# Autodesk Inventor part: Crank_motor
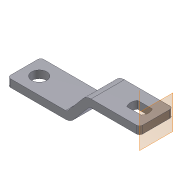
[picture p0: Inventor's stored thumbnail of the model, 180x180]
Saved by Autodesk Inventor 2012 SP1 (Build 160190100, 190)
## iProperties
Created: 2006-03
Part Number: Crank_motor
Document SubType Name: Modeling
Material: Stainless Steel, 440C
Mass: 73.5464 g
Surface Area: 52.6545 cm^2
Volume: 9.48986 cm^3
Density: 7.75 g/cm^3
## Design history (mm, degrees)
sketch "Sketch1"
  geometry: L1 (0, 0)-(-34.15, 0); L2 (0, 0)-(12.586, -15); L3 (12.586, -15)-(53.05, -15)
  constraints: 6 end point, 1 horizontal, 1 parallel
  dimensions: "d0" = 130 deg angle of L2 L1; "d1" = 87.2 horizontal distance of L3.end L1.end; "d2" = 34.15 distance of L1.start L1.end; "d3" = 15 distance between parallel lines of L3 L1
workplane "Work Plane1"
sketch "Sketch2"
  geometry: L1 (-11, 2.5)-(11, 2.5); L2 (11, 2.5)-(11, -2.5); L3 (11, -2.5)-(-11, -2.5); L4 (-11, -2.5)-(-11, 2.5); L5 (-11, 2.5)-(11, -2.5); 2 further points
  constraints: 10 end point, 2 parallel, 1 coincident, 1 horizontal, 1 midpoint, 1 perpendicular
  dimensions: "d4" = 22 distance of L1.start L1.end; "d5" = 5 distance of L3.end L1.start
sweep "Sweep1" sketch "Sketch2" dims "d6" = 0
fillet "Fillet1" dims "d7" = 7
fillet "Fillet2" dims "d8" = 2
sketch "Sketch4"
  geometry: L1 (-95.92, 11)-(26.16, 11) reference; L2 (0, 28.6)-(0, -2.2) reference; L3 (-15.823, 7.425)-(-6.178, 7.425); L4 (-6.178, 7.425)-(-6.178, 14.575); L5 (-6.178, 14.575)-(-15.823, 14.575); L6 (-15.823, 14.575)-(-15.823, 7.425); L7 (-15.823, 7.425)-(-6.178, 14.575); A1 r 6 centre (-10.997, 11) between (-6.178, 7.425) and (-6.178, 14.575); A2 r 6 centre (-11.004, 11) between (-15.823, 14.575) and (-15.823, 7.425); 2 further points
  constraints: 10 end point, 4 point on circle, 3 point on line, 2 centre point, 2 parallel, 1 equal radius, 1 horizontal, 1 midpoint, 1 perpendicular
  dimensions: "d18" = 9.645 distance of L3.start L3.end; "d19" = 7.15 distance of L5.end L3.start; "d20" = 6.178 distance from line of L3.end L2; "d21" = 6 radius of A2
extrude "Extrusion3" cut sketch "Sketch4" stored distance "d22" = 10; taper "d23" = 0 deg
sketch "Sketch3"
  geometry: L1 (-8.72, 11)-(113.36, 11) reference; L2 (0, 22)-(0, 0) reference; C1 r 5 at (10, 11); 1 further point
  constraints: 1 centre point, 1 point on line
  dimensions: "d9" = 10 distance from line of C1.centre L2; "d10" = 10 diameter of C1
extrude "Extrusion1" cut sketch "Sketch3" stored distance "d11" = 10; taper "d12" = 0 deg
fillet "Fillet3" dims "d17" = 2
workaxis "Work Axis2"
  workplane "Work Plane3"
body "Solid1"
